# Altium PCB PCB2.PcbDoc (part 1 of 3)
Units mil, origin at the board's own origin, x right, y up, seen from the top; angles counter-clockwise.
Board outline 10275.59 x 4173.23 mil, 2 copper layers (Top Layer, Bottom Layer); 158 components, 159 nets, 776 pads, 338 vias.
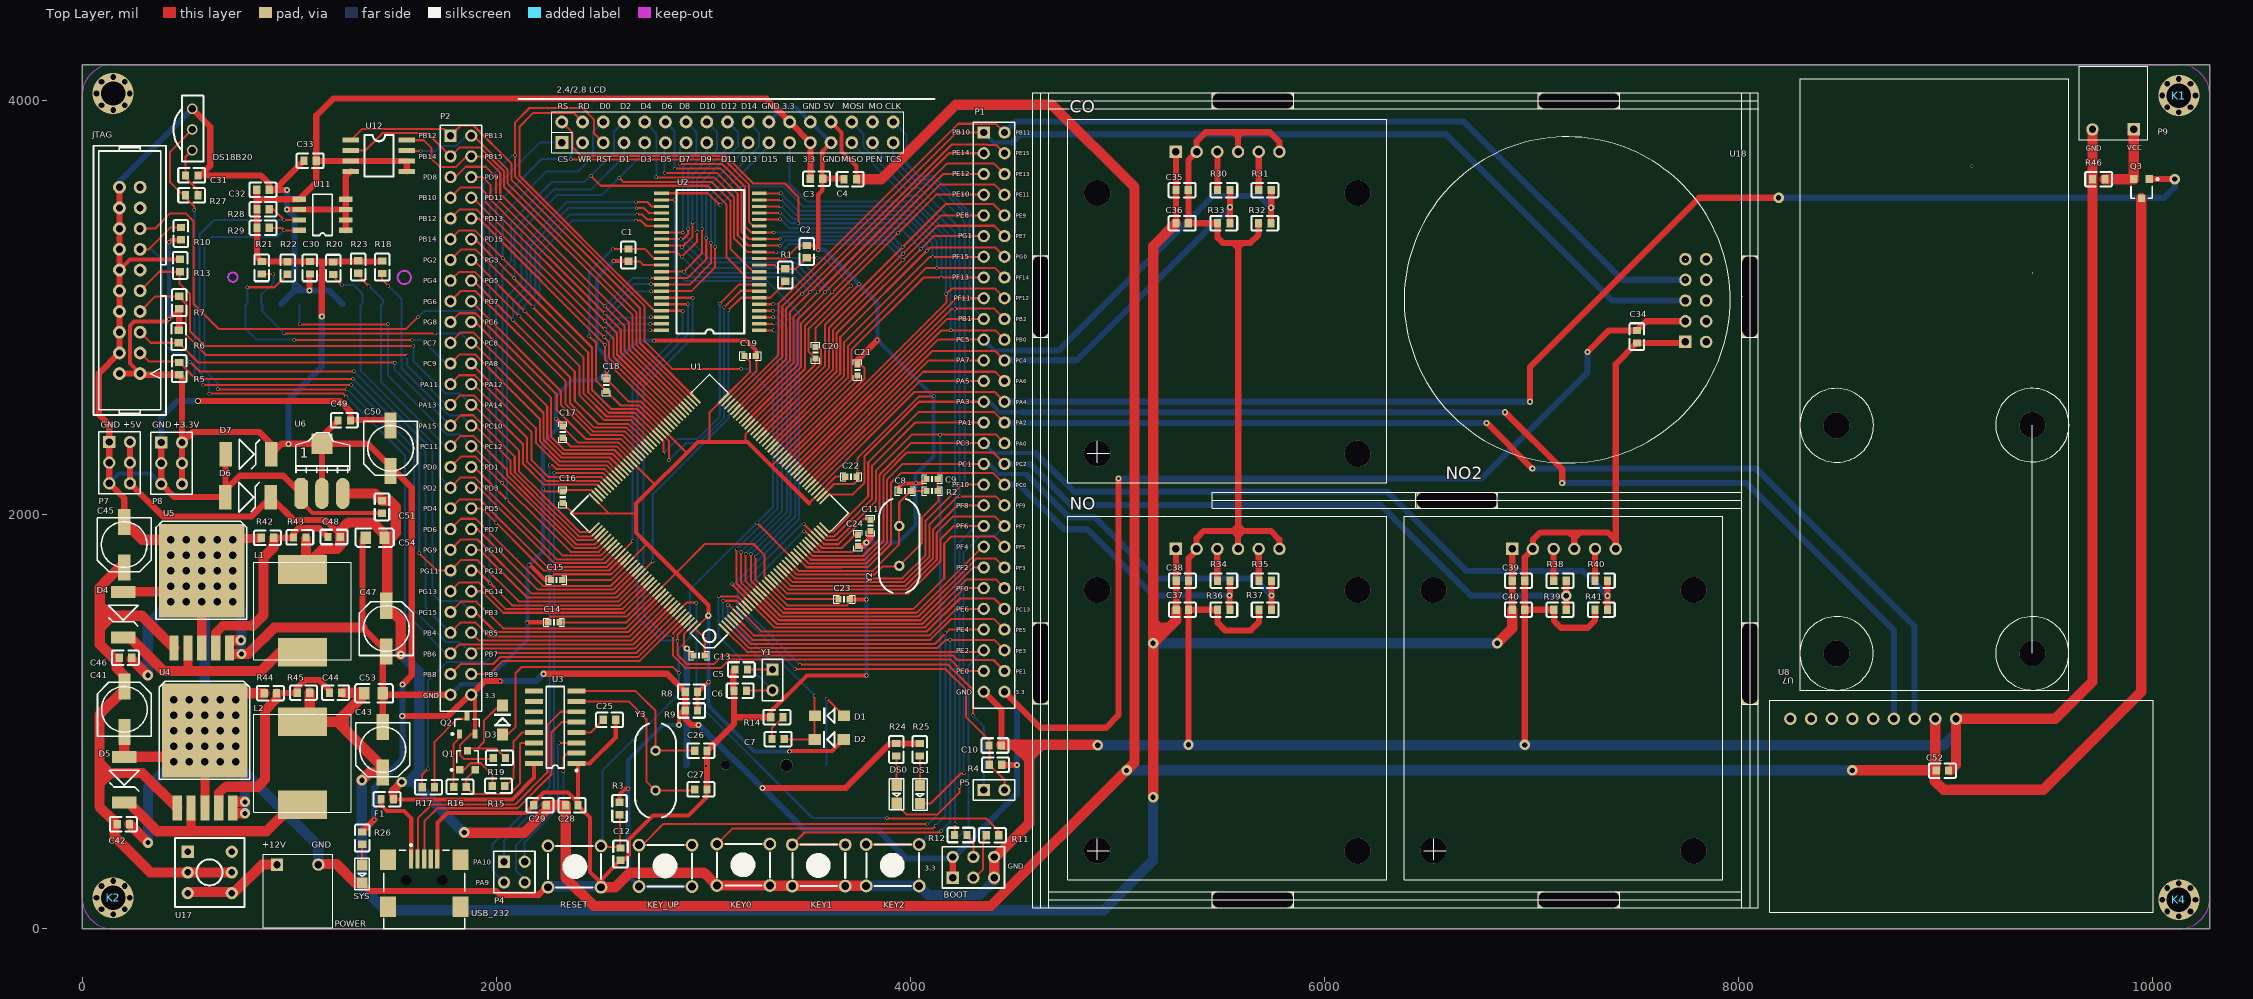
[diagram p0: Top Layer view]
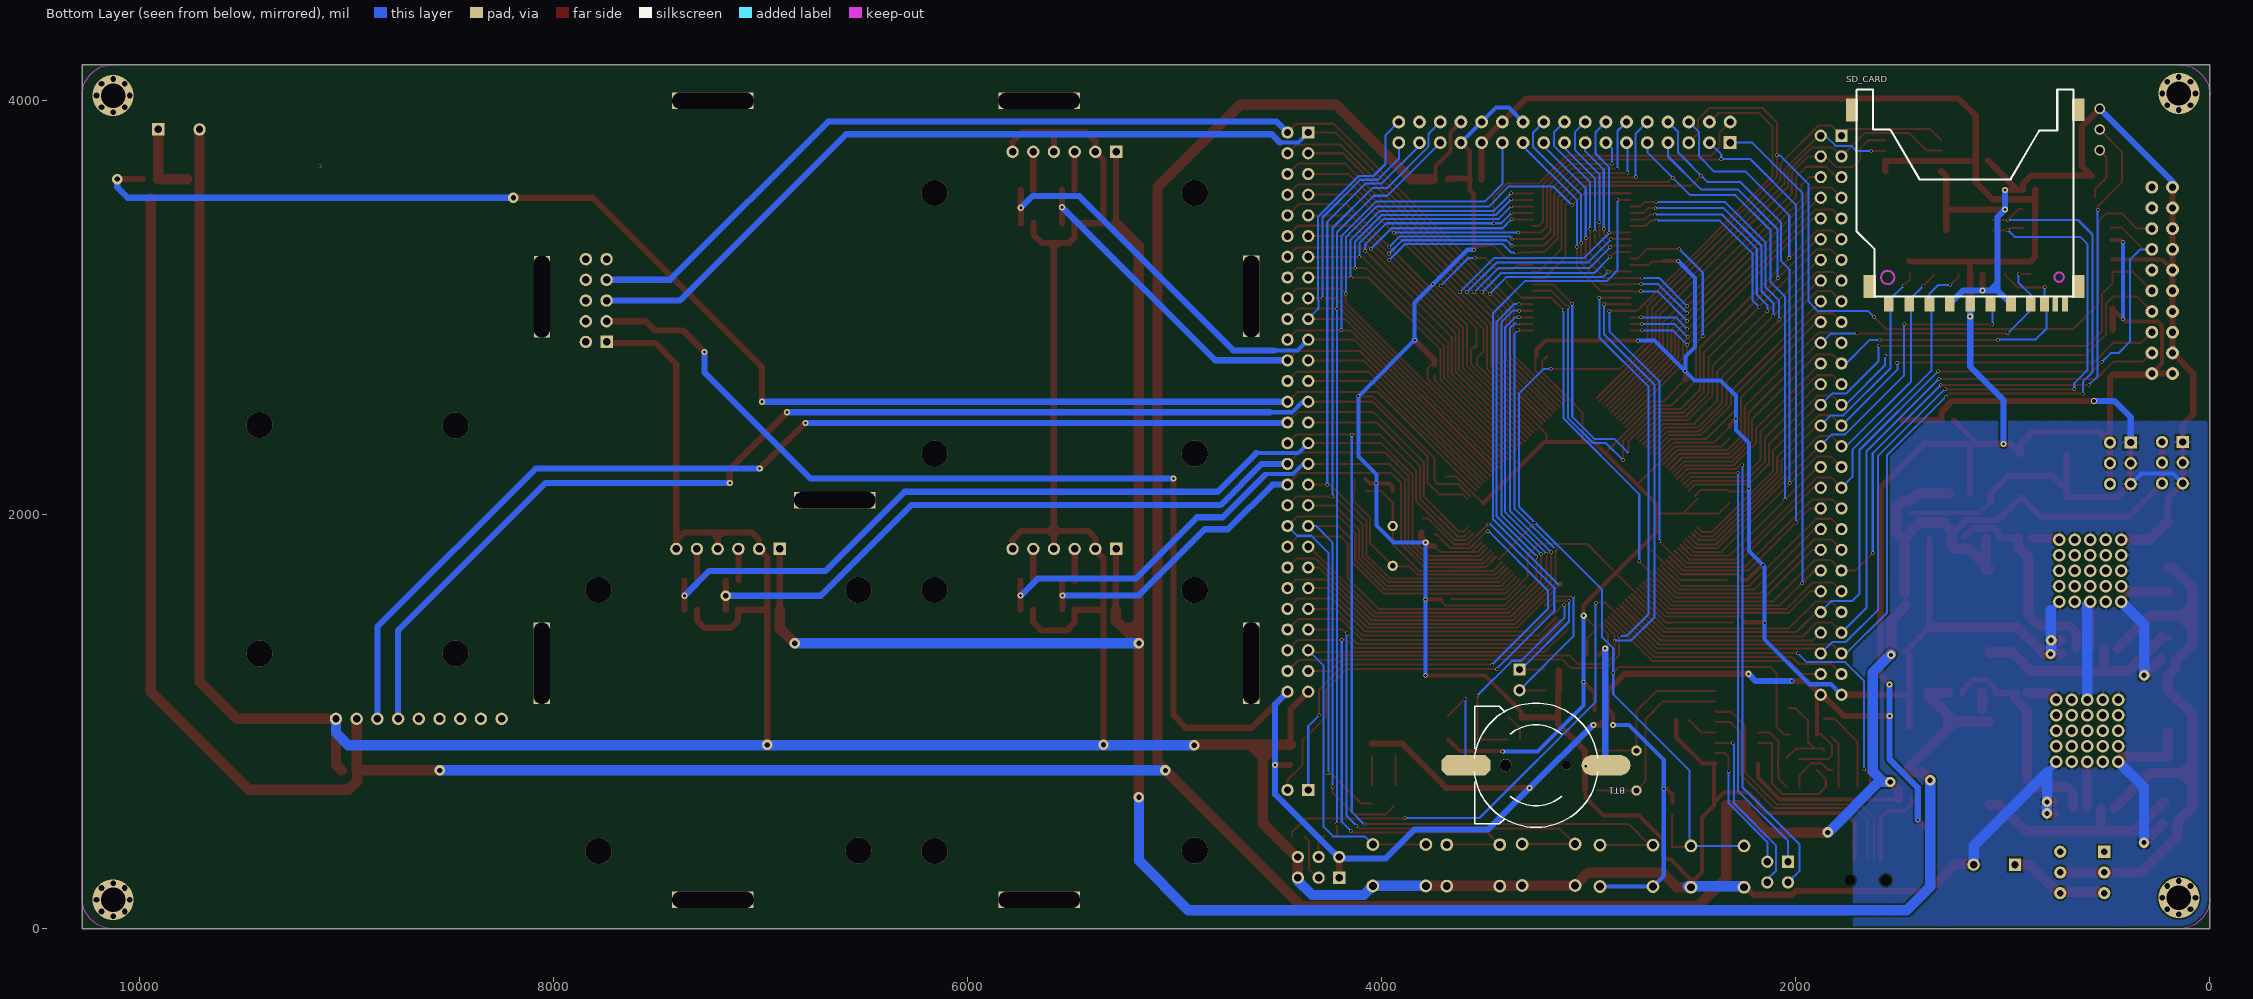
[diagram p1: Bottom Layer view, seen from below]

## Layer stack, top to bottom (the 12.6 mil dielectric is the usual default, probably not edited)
Top Layer: signal copper 1.4
Dielectric: dielectric 12.6, FR-4, Dk 4.8
Bottom Layer: signal copper 1.4

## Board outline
0,4173.23 10275.59,4173.23 10275.59,0 10217.37,0 0,0

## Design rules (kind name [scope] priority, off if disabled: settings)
Clearance [All] p1: gap=8
HoleSize [All] p1: absolutevalues=TRUE maxlimit=400 minlimit=1 maxpercent=80.000 minpercent=20.000
HoleToHoleClearance [All] p1: gap=5 allowstackedmicrovias=TRUE
PolygonConnect [All] p1: connectstyle=Relief reliefconductorwidth=10 reliefentries=4 polygonreliefangle="90 Angle" airgapwidth=10
RoutingVias [All] p1: holewidth=28 width=50 viastyle="Through Hole" minholewidth=28 minwidth=50 maxholewidth=28 maxwidth=50
SilkToSilkClearance [All] p1: silktosilkclearance=0
SilkToSolderMaskClearance [IsPad] p1: minsilkscreentomaskgap=0 clearancetoexposedcopper=TRUE
SolderMaskExpansion [All] p1: expansion=4
Width VCC3.3M [InNet('VCC3.3M')] p1: maxlimit=30 minlimit=10 preferedwidth=10
Width VCC3.3 [InNet('VCC3.3')] p2: maxlimit=30 minlimit=10 preferedwidth=10
Width VCC6 [InNet('VCC6')] p3: maxlimit=50 minlimit=10 preferedwidth=10
Width GND [InNet('GND')] p4: maxlimit=50 minlimit=10 preferedwidth=10
Width VCC5 [InNet('VCC5')] p5: maxlimit=50 minlimit=10 preferedwidth=10
Width [All] p6: maxlimit=50 minlimit=10 preferedwidth=10
24 further rules are at their usual default settings.

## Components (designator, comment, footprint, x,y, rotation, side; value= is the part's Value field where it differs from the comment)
"2.4/2.8 LCD" "TFT_LCD" LCD 3322,2791 r0 top
BOOT "Header 3X2" HDR2X3 4204.37,246.61 r0 top
BT1 "Battery" BATM 3254.37,789.61 r270 bottom
C1 "Cap" 0603A 2638.37,3282.61 r270 top
C2 "Cap" 0603A 3499.37,3239.61 r90 top
C3 "Cap" 0603A 3517,3622 r0 top
C4 "Cap" 0603A 3739.37,3619.61 r180 top
C5 "Cap" 0603A 3153.37,1251.61 r0 top
C6 "Cap" 0603A 3148.37,1149.61 r0 top
C7 "Cap" 0603A 3331.37,915.61 r0 top
C8 "Cap" 0603P 3974.37,2113.61 r0 top
C9 "Cap" 0603P 4104.37,2171.61 r0 top
C10 "Cap" 0603A 4439.37,884.61 r180 top
C11 "Cap" 0603P 3808,1947 r90 top
C12 "Cap" 0603A 2600,330 r90 top
C13 "Cap" 0603P 2979.37,1319.61 r0 top
C14 "Cap" 0603P 2278.37,1479.61 r0 top
C15 "Cap" 0603P 2291.37,1683.61 r0 top
C16 "Cap" 0603P 2321.37,2083.61 r270 top
C17 "Cap" 0603P 2321.37,2398.61 r270 top
C18 "Cap" 0603P 2531.37,2624.61 r270 top
C19 "Cap" 0603P 3226.37,2765.61 r180 top
C20 "Cap" 0603P 3541.37,2781.61 r270 top
C21 "Cap" 0603P 3744.37,2698.61 r270 top
C22 "Cap" 0603P 3713.37,2182.61 r180 top
C23 "Cap" 0603P 3680.37,1590.61 r180 top
C24 "Cap" 0603P 3746.37,1874.61 r90 top
C25 "Cap" 0603A 2517.37,1008.61 r0 top
C26 "Cap" 0603A 3018.37,859.61 r180 top
C27 "Cap" 0603A 3018.37,672.61 r180 top
C28 "Cap" 0603A 2395.37,595.61 r180 top
C29 "Cap" 0603A 2181.37,595.61 r0 top
C30 "Cap" 0603A 1100.37,3161.61 r90 top
C31 "Cap" 0603A 499.37,3637.61 r0 top
C32 "Cap" 0603A 843.37,3568.61 r0 top
C33 "Cap" 0603A 1131.37,3708.61 r180 top
C34 "Cap" 0603A 7508.37,2828.74 r90 top
C35 "Cap" 0603A 5282.37,3566.74 r0 top
C36 "Cap" 0603A 5282.37,3406.74 r0 top
C37 "Cap" 0603A 5283.37,1540.74 r0 top
C38 "Cap" 0603A 5283.37,1680.74 r0 top
C39 "Cap" 0603A 6906.37,1680.74 r0 top
C40 "Cap" 0603A 6906.37,1540.74 r0 top
C41 "Cap Pol2" CC6.56.5 204.37,1059.61 r270 top
C42 "Cap" 0603A 229.37,504.61 r180 top
C43 "Cap Pol1" CC6.56.5 1452.37,864.61 r90 top
C44 "Cap" 0603A 1254.37,1139.61 r180 top
C45 "Cap Pol2" CC6.56.5 203.37,1854.61 r90 top
C46 "Cap" 0603A 239.37,1308.61 r180 top
C47 "Cap Pol1" CC6.56.5 1469.37,1449.61 r270 top
C48 "Cap" 0603A 1247.37,1891.61 r180 top
C49 "Cap" 0603A 1236.37,2454.61 r0 top
C50 "Cap Pol1" CC6.56.5 1490,2320 r90 top
C51 "Cap" 0603A 1448.37,2066.61 r270 top
C52 "Cap" 0603A 8953.37,763.74 r0 top
C53 "Cap" 0805 1362.37,1136.61 r0 top
C54 "Cap" 0805 1460.24,1888.61 r180 top
CO "B4" chuanganqi 6299.91,2153.61 r90 top
D1 "1N4148" DIODE_SOP 3679.37,1027.61 r180 top
D2 "1N4148" DIODE_SOP 3678.37,913.61 r180 top
D3 "1N4148" DIODE_SOP 2030.37,937.61 r90 top
D4 "D1" SMBJ 199.37,1521.61 r270 top
D5 "D1" SMBJ 204.37,724.61 r270 top
D6 "SMBJ50.A" SMBJ 796.37,2084.61 r0 top
D7 "SMBJ3.3A" SMBJ 798.37,2291.61 r0 top
DS0 "LED0" SMDLED 3933.37,693.61 r270 top
DS1 "LED1" SMDLED 4046.37,691.61 r270 top
DS18B20 "Header 3" HS0038 532.37,3959.61 r270 top (schematic designator P6)
F1 "Res2" 0603A 1443.37,624.61 r0 top
JTAG "JTAG" JTAG_20 230.37,3130.61 r90 top
K1 "固定孔" 固定孔 10125.59,4023.23 r0 top
K2 "固定孔" 固定孔 150,150 r0 top
K3 "固定孔" 固定孔 150,4033.23 r0 top
K4 "固定孔" 固定孔 10125.59,140 r0 top
KEY0 "SW-PB" KEY_M 3321.37,208.61 r180 top
KEY1 "SW-PB" KEY_M 3685.37,205.61 r180 top
KEY2 "SW-PB" KEY_M 4042.37,206.61 r180 top
KEY_UP "SW-PB" KEY_M 2945.37,203.61 r180 top
L1 "Inductor" PCBComponent_1 1064.37,1534.61 r90 top
L2 "Inductor" PCBComponent_1 1064.37,799.61 r90 top
NO "B4" chuanganqi 6299.91,235.61 r90 top
NO2 "B4" chuanganqi 7923.88,235.61 r90 top
P1 "Header28X2" HEADER28X2 4354.37,3844.61 r270 top
P2 "Header28X2" HEADER28X2 1779.37,3829.61 r270 top
P4 "USART1" HDR2X2 2037.37,323.61 r270 top
P5 "Header 2" HDR1X2 4354.37,669.61 r0 top
P7 "Header 3X2" HDR2X3 131.37,2350.61 r270 top
P8 "Header 3X2" HDR2X3 382.37,2347.61 r270 top
P9 "Header 2" 接插件 9808.37,3809.74 r180 top
POWER "3-35V" 接插件 1041.37,359.74 r0 top (schematic designator IN)
Q1 "S8250" SOT-23R 1861.37,808.61 r0 top
Q2 "S8550" SOT-23B_N 1859.37,984.61 r90 top
Q3 "NPN" SOT-23R 9945.37,3578.61 r180 top
R1 "Res2" 0603A 3395.37,3126.61 r90 top
R2 "Res2" 0603P 4104.37,2113.61 r0 top
R3 "Res2" 0603A 2595.37,550.61 r90 top
R4 "10R" 0603A 4381.37,791.61 r0 top
R5 "Res2" 0603A 469.37,2674.61 r90 top
R6 "Res2" 0603A 466.37,2889.61 r270 top
R7 "Res2" 0603A 469.37,2993.61 r90 top
R8 "Res2" 0603A 2912.37,1144.61 r0 top
R9 "Res2" 0603A 2912.37,1053.61 r0 top
R10 "Res2" 0603A 477.37,3326.61 r90 top
R11 "Res2" 0603A 4366.37,451.61 r0 top
R12 "Res2" 0603A 4213.37,452.61 r0 top
R13 "Res2" 0603A 473.37,3172.61 r90 top
R14 "Res2" 0603A 3385.37,1021.61 r180 top
R15 "Res2" 0603A 1981.37,689.61 r0 top
R16 "Res2" 0603A 1795.37,684.61 r0 top
R17 "Res2" 0603A 1702.37,683.61 r180 top
R18 "Res2" 0603A 1449.37,3164.61 r90 top
R19 "Res2" 0603A 1985.37,824.61 r0 top
R20 "Res2" 0603A 1213.37,3219.61 r270 top
R21 "Res2" 0603A 867.37,3221.61 r270 top
R22 "Res2" 0603A 992.37,3220.61 r270 top
R23 "Res2" 0603A 1333.37,3225.61 r270 top
R24 "Res2" 0603A 3932.37,894.61 r270 top
R25 "Res2" 0603A 4045.37,894.61 r270 top
R26 "Res2" 0603A 1352.37,467.61 r270 top
R27 "Res2" 0603A 499.37,3541.61 r0 top
R28 "Res2" 0603A 844.37,3474.61 r0 top
R29 "Res2" 0603A 844.37,3384.61 r0 top
R30 "Res2" 0603A 5543.37,3566.74 r180 top
R31 "Res2" 0603A 5742.37,3566.74 r180 top
R32 "Res2" 0603A 5681.37,3406.74 r0 top
R33 "Res2" 0603A 5483.37,3406.74 r0 top
R34 "Res2" 0603A 5543.37,1680.74 r180 top
R35 "Res2" 0603A 5743.37,1680.74 r180 top
R36 "Res2" 0603A 5483.37,1540.74 r0 top
R37 "Res2" 0603A 5683.37,1540.74 r0 top
R38 "Res2" 0603A 7167.37,1680.74 r180 top
R39 "Res2" 0603A 7107.37,1540.74 r0 top
R40 "Res2" 0603A 7366.37,1680.74 r180 top
R41 "Res2" 0603A 7306.37,1540.74 r0 top
R42 "Res2" 0603A 925.37,1887.61 r180 top
R43 "Res2" 0603A 1021.37,1889.61 r0 top
R44 "Res2" 0603A 939.37,1137.61 r180 top
R45 "Res2" 0603A 1039.37,1139.61 r0 top
R46 "Res2" 0603A 9708.37,3619.61 r0 top
RESET "SW-PB" KEY_M 2250,400 r0 top
SD_CARD "SD_CARD" SDCARD_L 1452.37,3016.61 r0 bottom
SYS "PWR" SMDLED 1352.37,307.61 r270 top
U1 "stm32f103zet6" LQFP144 3099.6,1449.34 r135 top
U2 "IS62WV51216" TSOP44 3270.37,2889.61 r180 top
U3 "CH340G" SOP16M 2285.37,972.61 r90 top
U4 "LM2596ADJ" lm2596 592.37,956.61 r0 top
U5 "LM2596ADJ" lm2596 577.37,1728.61 r0 top
U6 "AMS1117-3.3" AMS1117 1058.37,2101.61 r0 top
U7 "qibeng" qibeng 9594.91,1152.61 r90 top
U8 "wuxian" wuxain 9049.37,1013.74 r270 top
U11 "24C02" SOP-8 1273.37,3372.61 r180 top
U12 "W25Q25" SOIC-8 1298.37,3807.61 r0 top
U17 "BUTTON" BTN8.5*8.5 510.37,371.74 r0 top
U18 "CO2" CO2 7171.91,3036.61 r0 top
USB_232 "USB" USB/SM0.8-6H5 1652.37,27.74 r270 top
Y1 "32.768K" HDR1X2 3334.37,1251.61 r270 top
Y2 "8M" XTAL_US 3946.37,1944.61 r270 top
Y3 "12MHZ" XTAL_US 2769.37,859.61 r270 top

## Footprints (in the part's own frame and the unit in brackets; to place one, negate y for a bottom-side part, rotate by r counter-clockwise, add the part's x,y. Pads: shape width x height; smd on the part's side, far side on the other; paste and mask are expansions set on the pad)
0603A [mil]
  rect 35x40 smd: 1(0,0) 2(60,0)
  silkscreen extent -35,-35 95,35
0603P [mil]
  rect 30x30 smd: 1(-27,0) 2(27.5,-0.06)
  silkscreen extent -50,-20 50,20
0805 [mil]
  rect 50x60 smd: 1(90,0) 2(0,0)
  silkscreen extent -45,-45 140,45
AMS1117 [mil]
  oct 65x150 smd: 1(0.03,-0.06)
  oval 65x150 smd: 2(100.03,-0.06) 3(200.03,-0.06)
  rect 100x100 smd: 4(100.03,239.94)
  silkscreen extent -26,100 234,293
BATM [mm]
  round 1.1 hole 1.1 unplated: 0(0,3.748)
  round 1.5 hole 1.5 unplated: 0(0.025,-3.752)
  oct 2.5x6 smd mask+0.102: 1(0,-8.602)
  oval 2.5x6 smd: 2(0,8.598)
  silkscreen extent -7.62,-7.58 7.62,7.57
BTN8.5*8.5 [mm]
  rect 1.5x1.5 hole 0.8: 1(0,0)
  round 1.5 hole 0.8: 2(0,-2.54) 3(0,-5.08) 4(5.4,-5.08) 5(5.4,-2.54) 6(5.4,0)
  silkscreen extent -1.55,-6.79 6.95,1.71
CC6.56.5 [mm]
  rect 3.2x1.5 smd: 1(-2.794,0) 2(2.8,0)
  silkscreen extent -3.3,-3.3 3.3,3.3
chuanganqi [mil]
  rect 60x60 hole 36: 1(1598.24,1017.72)
  round 60 hole 36: 2(1598.24,917.72) 3(1598.24,817.72) 4(1598.24,717.72) 5(1598.24,617.72) 6(1598.24,517.72)
  silkscreen extent 0,0 1756,1539
CO2 [mil]
  rect 60x60 hole 36: 1(570.87,-203.15)
  round 60 hole 36: 2(670.87,-203.15) 3(570.87,-103.15) 4(670.87,-103.15) 5(570.87,-3.15) 6(670.87,-3.15) 7(570.87,96.85) 8(670.87,96.85) 9(570.87,196.85) 10(670.87,196.85)
  silkscreen extent -787,-787 787,787
DIODE_SOP [mm]
  rect 1.5x1.3 smd: 1(0,0) 2(3.556,0)
  silkscreen extent 1.14,-1.02 2.56,1.02
HDR1X2 [mm] "Connector; Header; 2 Position"
  rect 1.5x1.5 hole 0.9: 1(0,0)
  round 1.5 hole 0.9: 2(2.54,0)
  silkscreen extent -1.27,-1.27 3.81,1.27
HDR2X2 [mm] "Connector; Header; 2x2 Position"
  rect 1.5x1.5 hole 0.9: 1(0,0)
  round 1.5 hole 0.9: 2(0,2.54) 3(2.54,0) 4(2.54,2.54)
  silkscreen extent -1.27,-1.27 3.81,3.81
HDR2X3 [mm] "Connector; Header; 3x2 Position"
  rect 1.5x1.5 hole 0.9: 1(0,0)
  round 1.5 hole 0.9: 2(0,2.54) 3(2.54,0) 4(2.54,2.54) 5(5.08,0) 6(5.08,2.54)
  silkscreen extent -1.27,-1.27 6.35,3.81
HEADER28X2 [mm]
  rect 1.5x1.5 hole 0.9: 1(0,0)
  round 1.5 hole 0.9: 2(0,2.54) 3(2.54,0) 4(2.54,2.54) 5(5.08,0) 6(5.08,2.54) 7(7.62,0) 8(7.62,2.54) 9(10.16,0) 10(10.16,2.54) 11(12.7,0) 12(12.7,2.54) 13(15.24,0) 14(15.24,2.54) 15(17.78,0) 16(17.78,2.54) 17(20.32,0) 18(20.32,2.54) 19(22.86,0) 20(22.86,2.54) 21(25.4,0) 22(25.4,2.54) 23(27.94,0) 24(27.94,2.54) 25(30.48,0) 26(30.48,2.54) 27(33.02,0) 28(33.02,2.54) 29(35.56,0) 30(35.56,2.54) 31(38.1,0) 32(38.1,2.54) 33(40.64,0) 34(40.64,2.54) 35(43.18,0) 36(43.18,2.54) 37(45.72,0) 38(45.72,2.54) 39(48.26,0) 40(48.26,2.54) 41(50.8,0) 42(50.8,2.54) 43(53.34,0) 44(53.34,2.54) 45(55.88,0) 46(55.88,2.54) 47(58.42,0) 48(58.42,2.54) 49(60.96,0) 50(60.96,2.54) 51(63.5,0) 52(63.5,2.54) 53(66.04,0) 54(66.04,2.54) 55(68.58,0) 56(68.58,2.54)
  silkscreen extent -1.27,-1.27 70.61,3.81
HS0038 [mm]
  round 1.3 hole 0.889: 1(0,0) 2(2.54,0) 3(5.08,0)
  silkscreen extent -1.65,-2.32 6.48,1.4
JTAG_20 [mil]
  round 62 hole 35: 1(-450,-50) 2(-450,50) 3(-350,-50) 4(-350,50) 5(-250,-50) 6(-250,50) 7(-150,-50) 8(-150,50) 9(-50,-50) 10(-50,50) 11(50,-50) 12(50,50) 13(150,-50) 14(150,50) 15(250,-50) 16(250,50) 17(350,-50) 18(350,50) 19(450,-50) 20(450,50)
  silkscreen extent -650,-175 650,175
KEY_M [mil]
  round 62 hole 38: 1(0,0) 1(255.91,0) 2(0,-200) 2(255.91,-200)
  silkscreen extent 0,-200 255,0
LCD [mil]
  rect 62x62 hole 35: 1(-1005,1005)
  round 62 hole 35: 2(-1005,1105) 3(-905,1005) 4(-905,1105) 5(-805,1005) 6(-805,1105) 7(-705,1005) 8(-705,1105) 9(-605,1005) 10(-605,1105) 11(-505,1005) 12(-505,1105) 13(-405,1005) 14(-405,1105) 15(-305,1005) 16(-305,1105) 17(-205,1005) 18(-205,1105) 19(-105,1005) 20(-105,1105) 21(-5,1005) 22(-5,1105) 23(95,1005) 24(95,1105) 25(195,1005) 26(195,1105) 27(295,1005) 28(295,1105) 29(395,1005) 30(395,1105) 31(495,1005) 32(495,1105) 33(595,1005) 34(595,1105)
  silkscreen extent -1215,955 795,1215
lm2596 [mil]
  rect 45x120 smd: 1(-133,-373.35) 2(-66,-373.35) 3(1,-373.35) 4(68,-373.35) 5(135,-373.35)
  rect 413.39x452.76 smd: 3(0,0)
  silkscreen extent -220,-235 217,239
LQFP144 [mil]
  rect 70.87x10 smd: 1(-0.35,0.02) 2(-0.35,-19.66) 3(-0.35,-39.35) 4(-0.35,-59.03) 5(-0.35,-78.72) 6(-0.35,-98.4) 7(-0.35,-118.09) 8(-0.35,-137.77) 9(-0.35,-157.46) 10(-0.35,-177.14) 11(-0.35,-196.83) 12(-0.35,-216.51) 13(-0.35,-236.2) 14(-0.35,-255.88) 15(-0.35,-275.57) 16(-0.35,-295.25) 17(-0.35,-314.94) 18(-0.35,-334.62) 19(-0.35,-354.31) 20(-0.35,-373.99) 21(-0.35,-393.68) 22(-0.35,-413.36) 23(-0.35,-433.05) 24(-0.35,-452.73) 25(-0.35,-472.42) 26(-0.35,-492.1) 27(-0.35,-511.79) 28(-0.35,-531.47) 29(-0.35,-551.16) 30(-0.35,-570.84) 31(-0.35,-590.53) 32(-0.35,-610.21) 33(-0.35,-629.9) 34(-0.35,-649.58) 35(-0.35,-669.27) 36(-0.35,-688.95) 73(885.47,-688.95) 74(885.47,-669.27) 75(885.47,-649.58) 76(885.47,-629.9) 77(885.47,-610.21) 78(885.47,-590.53) 79(885.47,-570.84) 80(885.47,-551.16) 81(885.47,-531.47) 82(885.47,-511.79) 83(885.47,-492.1) 84(885.47,-472.42) 85(885.47,-452.73) 86(885.47,-433.05) 87(885.47,-413.36) 88(885.47,-393.68) 89(885.47,-373.99) 90(885.47,-354.31) 91(885.47,-334.62) 92(885.47,-314.94) 93(885.47,-295.25) 94(885.47,-275.57) 95(885.47,-255.88) 96(885.47,-236.2) 97(885.47,-216.51) 98(885.47,-196.83) 99(885.47,-177.14) 100(885.47,-157.46) 101(885.47,-137.77) 102(885.47,-118.09) 103(885.47,-98.4) 104(885.47,-78.72) 105(885.47,-59.03) 106(885.47,-39.35) 107(885.47,-19.66) 108(885.47,0.02)
  rect 10x70.87 smd: 37(98.07,-787.38) 38(117.76,-787.38) 39(137.44,-787.38) 40(157.13,-787.38) 41(176.81,-787.38) 42(196.5,-787.38) 43(216.18,-787.38) 44(235.87,-787.38) 45(255.55,-787.38) 46(275.24,-787.38) 47(294.92,-787.38) 48(314.61,-787.38) 49(334.29,-787.38) 50(353.98,-787.38) 51(373.66,-787.38) 52(393.35,-787.38) 53(413.03,-787.38) 54(432.72,-787.38) 55(452.4,-787.38) 56(472.09,-787.38) 57(491.77,-787.38) 58(511.46,-787.38) 59(531.14,-787.38) 60(550.83,-787.38) 61(570.51,-787.38) 62(590.2,-787.38) 63(609.88,-787.38) 64(629.57,-787.38) 65(649.25,-787.38) 66(668.94,-787.38) 67(688.62,-787.38) 68(708.31,-787.38) 69(727.99,-787.38) 70(747.68,-787.38) 71(767.36,-787.38) 72(787.05,-787.38) 109(787.05,98.45) 110(767.36,98.45) 111(747.68,98.45) 112(727.99,98.45) 113(708.31,98.45) 114(688.62,98.45) 115(668.94,98.45) 116(649.25,98.45) 117(629.57,98.45) 118(609.88,98.45) 119(590.2,98.45) 120(570.51,98.45) 121(550.83,98.45) 122(531.14,98.45) 123(511.46,98.45) 124(491.77,98.45) 125(472.09,98.45) 126(452.4,98.45) 127(432.72,98.45) 128(413.03,98.45) 129(393.35,98.45) 130(373.66,98.45) 131(353.98,98.45) 132(334.29,98.45) 133(314.61,98.45) 134(294.92,98.45) 135(275.24,98.45) 136(255.55,98.45) 137(235.87,98.45) 138(216.18,98.45) 139(196.5,98.45) 140(176.81,98.45) 141(157.13,98.45) 142(137.44,98.45) 143(117.76,98.45) 144(98.07,98.45)
  silkscreen extent -32,-819 917,130
PCBComponent_1 [mm]
  rect 3.5x6 smd: 1(-5.08,0) 2(5.08,0)
  silkscreen extent -6,-5.99 6,6.01
qibeng [mil]
  silkscreen extent 0,0 2953,1300
SDCARD_L [mm]
  rect 1.2x1.8 smd: 1(0,0) 2(-2.489,0) 3(-4.983,-0.009) 4(-7.483,-0.009) 5(-9.983,-0.009) 6(-12.483,-0.009) 7(-14.908,-0.009) 9(2.517,-0.009)
  rect 1.1x1.8 smd: 8(-16.612,0)
  rect 0.7x1.8 smd: 10(-17.908,-0.009) 12(-19.101,0)
  rect 1.5x2.8 smd: 11(-20.726,-23.834) 11(-20.726,-2.143) 11(4.826,-2.143) 11(7.01,-23.784)
  Keep-Out Layer circle w0.254: c2.642,-3.26 r0.82
  Keep-Out Layer circle w0.254: c-18.39,-3.3 r0.58
  silkscreen extent -20.13,-26.3 6.44,-0.9
SMBJ [mm]
  rect 1.5x3 smd: 1(-2.667,0) 2(2.921,0)
  silkscreen extent -1.02,-1.85 1.52,1.83
SMDLED [mm]
  rect 1.4x1.27 smd: 1(0.001,-0.002) 2(2.211,-0.002)
  silkscreen extent -0.8,-0.89 3.01,0.89
SOIC-8 [mil]
  rect 80x24 smd: 1(0,0) 2(0,-50.06) 3(0,-100.06) 4(0,-150.06) 5(270,-150) 6(270,-100) 7(270,-50) 8(270,0)
  silkscreen extent 65,-175 205,25
SOP16M [mm]
  rect 0.6x2.2 smd: 1(-4.445,-2.6) 2(-3.175,-2.6) 3(-1.905,-2.6) 4(-0.635,-2.6) 5(0.635,-2.6) 6(1.905,-2.6) 7(3.175,-2.6) 8(4.445,-2.6) 9(4.445,2.6) 10(3.175,2.6) 11(1.905,2.6) 12(0.635,2.6) 13(-0.635,2.6) 14(-1.905,2.6) 15(-3.175,2.6) 16(-4.445,2.6)
  silkscreen extent -5.42,-2.72 5,1.1
SOP-8 [mil]
  rect 65x25 smd: 1(0,0) 2(0,-50) 3(0,-100) 4(0,-150) 5(224.41,-150) 6(224.41,-100) 7(224.41,-50) 8(224.41,0)
  silkscreen extent 65,-175 159,25
SOT-23B_N [mm] "SOT23, 3-Leads, Body 2.9x1.3mm, Pitch 0.95mm, Lead Span 2.4mm, IPC Medium Density"
  rect 1.15x0.6 smd: 1(-1.125,0.95) 2(-1.125,-0.95) 3(1.125,0)
  silkscreen extent -1.25,-1.5 0.7,1.92, body extent -0.7,-1.5 0.7,1.5, height 1.14
SOT-23R [mm]
  rect 0.9x0.95 smd: 1(-0.95,-1.048) 2(0.95,-1.048) 3(0,1.302)
  silkscreen extent -2.07,-1.17 1.3,1.3
TSOP44 [mm]
  rect 1.8x0.4 smd: 1(-0.009,0.001) 2(-0.009,-0.799) 3(-0.009,-1.599) 4(-0.009,-2.399) 5(-0.009,-3.199) 6(-0.009,-3.999) 7(-0.009,-4.799) 8(-0.009,-5.599) 9(-0.009,-6.399) 10(-0.009,-7.199) 11(-0.009,-7.999) 12(-0.009,-8.799) 13(-0.009,-9.599) 14(-0.009,-10.399) 15(-0.009,-11.199) 16(-0.009,-11.999) 17(-0.009,-12.799) 18(-0.009,-13.599) 19(-0.009,-14.399) 20(-0.009,-15.199) 21(-0.009,-15.999) 22(-0.009,-16.799) 23(11.991,-16.799) 24(11.991,-15.999) 25(11.991,-15.199) 26(11.991,-14.399) 27(11.991,-13.599) 28(11.991,-12.799) 29(11.991,-11.999) 30(11.991,-11.199) 31(11.991,-10.399) 32(11.991,-9.599) 33(11.991,-8.799) 34(11.991,-7.999) 35(11.991,-7.199) 36(11.991,-6.399) 37(11.991,-5.599) 38(11.991,-4.799) 39(11.991,-3.999) 40(11.991,-3.199) 41(11.991,-2.399) 42(11.991,-1.599) 43(11.991,-0.799) 44(11.991,0.001)
  silkscreen extent 1.83,-17.2 10.16,0.4
USB/SM0.8-6H5 [mm]
  rect 2.3x0.5 smd: 1(-7.85,-1.6) 2(-7.85,-0.8) 3(-7.85,0) 4(-7.85,0.8) 5(-7.85,1.6)
  rect 2.5x2 smd: 6(-7.75,4.45) 7(-1.996,4.45) 8(-7.75,-4.45) 9(-1.996,-4.45)
  round 0.6 hole 1.27 unplated: MH1(-5.25,2.2) MH2(-5.25,-2.2)
  silkscreen extent -9.67,-4.95 0.7,4.95
wuxain [mil]
  round 60 hole 36: 1(0,0) 2(0,-100) 3(0,-200) 4(0,-300) 5(0,-400) 6(0,-500) 7(0,-600) 8(0,-700) 9(0,-800)
  silkscreen extent -91,-900 933,953
XTAL_US [mil]
  round 50 hole 28: 1(0,0) 2(192.13,0)
  silkscreen extent -131,-98 323,98
固定孔 [mil]
接插件 [mil]
  rect 60x60 hole 36: 1(-100,-50)
  round 60 hole 36: 2(100,-50)
  silkscreen extent -167,-354 167,0

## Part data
BOOT P7 P8: "Header, 3-Pin, Dual row"
BT1: "Multicell Battery"
C1 C2 C3 C4 C5 C6 C7 C8 C9 C10 C11 C12 C13 C14 C15 C16 C17 C18 C19 C20 C21 C22 C23 C24 C25 C26 C27 C28 C29 C30 C31 C32 C33 C34 C35 C36 C37 C38 C39 C40 C42 C44 C46 C48 C49 C51 C52 C53 C54: "Capacitor"
C41 C45: "Polarized Capacitor (Axial)"
C43 C47 C50: "Polarized Capacitor (Radial)"
D1 D2: library part "Diode 1N4148", "High Conductance Fast Diode"
D3: library part "Diode BAS116", "Silicon Low Leakage Diode"
D6 D7: library part D1
DS0: "Typical INFRARED GaAs LED"
DS1 SYS: library part LED0, "Typical INFRARED GaAs LED"
DS18B20: "Header, 3-Pin"
F1 R1 R2 R3 R5 R6 R7 R8 R9 R10 R11 R12 R13 R14 R15 R16 R17 R18 R19 R20 R21 R22 R23 R24 R25 R26 R27 R28 R29 R30 R31 R32 R33 R34 R35 R36 R37 R38 R39 R40 R41 R42 R43 R44 R45 R46: "Resistor"
KEY0 KEY1 KEY2 KEY_UP RESET: "Switch"
P4: library part "Header 2X2", "Header, 2-Pin, Dual row"
P5 P9: "Header, 2-Pin"
POWER: library part "Header 2", "Header, 2-Pin"
Q1: library part NPN, "NPN Bipolar Transistor"
Q2: library part PNP, "PNP Bipolar Transistor"
Q3: "NPN Bipolar Transistor"
R4: library part Res2, "Resistor"
Y1 Y2 Y3: library part XTAL, "Crystal Oscillator"

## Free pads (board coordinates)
  rect 393.7x78.74 hole 78.74 slot 393.7 at 0 deg: 1(5652.91,139.98) 2(7228.91,139.98) 7(5653.91,3997.61) 8(7228.91,3997.87) 9(6640.69,2069.74)
  rect 78.74x393.7 hole 78.74 slot 393.7 at 90 deg: 3(4629.91,1282.61) 4(4629.91,3053.61) 5(8055.72,1281.61) 6(8054.91,3052.61)

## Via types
v1: diameter 16, hole 12, Top Layer to Bottom Layer, 183 vias
v2: diameter 60, hole 36, Top Layer to Bottom Layer, 50 vias
v3: diameter 27.56, hole 27.56, Top Layer to Bottom Layer, 32 vias
v4: diameter 30, hole 15, Top Layer to Bottom Layer, 27 vias
v5: diameter 50, hole 25, Top Layer to Bottom Layer, 19 vias
v6: diameter 125.98, hole 125.98, Top Layer to Bottom Layer, 16 vias
v7: diameter 20, hole 15, Top Layer to Bottom Layer, 4 vias
v8: diameter 196.85, hole 118.11, Top Layer to Bottom Layer, 4 vias
v9: diameter 30, hole 20, Top Layer to Bottom Layer, 1 vias
v10: diameter 40, hole 20, Top Layer to Bottom Layer, 1 vias
v11: diameter 50, hole 28, Top Layer to Bottom Layer, 1 vias

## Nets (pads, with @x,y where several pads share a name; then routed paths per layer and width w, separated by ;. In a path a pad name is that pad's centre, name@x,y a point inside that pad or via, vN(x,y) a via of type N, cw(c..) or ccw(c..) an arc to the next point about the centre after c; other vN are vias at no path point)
BOOT0: R11.2 R17.2 U1.138 | length 4204.2
  Top Layer w10: R17.2@1642.37,683.61 1642.37,744.61 v1(1669.37,771.61) ; v1(1991.37,1330.61) 2675.15,1330.61 U1.138@2877.13,1532.59 ; U1.138@2876.89,1532.86 2918.64,1574.61 v1(2966.37,1574.61) ; v1(3885.37,534.61) 3887.37,532.61 4365.37,532.61 4433.37,464.61 R11.2@4433.37,445.61
  Bottom Layer w10: v1(1669.37,771.61) 1670.37,772.61 1670.37,1196.75 1761.23,1287.61 1761.75,1287.08 1947.84,1287.08 v1(1991.37,1330.61) ; v1(2966.37,1574.61) 2966.37,1095.61 3527.37,534.61 v1(3885.37,534.61)
BOOT1: "2.4/2.8 LCD.29" P1.20 R12.1 U1.48 | length 4951
  Top Layer w10: U1.48@3433.9,2228.56 4198.95,2993.61 v1(4215.37,2993.61) ; R12.1@4215.37,447.61 v1(4215.37,507.61) ; v1@4215.37,2994.61 4404.37,2994.61 P1.20@4454.37,2944.61
  Bottom Layer w10: 3717,3796 3973.39,3539.61 4038.37,3539.61 4215.37,3362.61 v1(4215.37,2993.61) v1(4215.37,507.61)
CH340_D+: U3.5 USB_232.3 | length 1243.6
  Top Layer w10: USB_232.3@1653.37,326.74 1653.37,518.61 1716.37,581.61 2103.37,581.61 2266.37,744.61 2266.37,947.61 2316.37,997.61 U3.5@2387.73,997.61
CH340_D-: U3.6 USB_232.2 | length 1313.1
  Top Layer w10: USB_232.2@1621.37,332.74 1621.37,532.61 1688.37,599.61 2091.37,599.61 2246.37,754.61 2246.37,982.61 2311.37,1047.61 U3.6@2387.73,1047.61
CO_1: P1.24 R30.1 R33.2 U1.44 | length 2794.2
  Top Layer w10: U1.44@3489.35,2173.15 4105.81,2789.61 4409.37,2789.61 P1.24@4454.37,2744.61
  Top Layer w30: R33.2@5543.37,3406.74 v4(5543.37,3483.74) R30.1@5543.37,3566.74
  Bottom Layer w30: P1.24@4454.37,2744.61 4804.24,2744.61 v4(5543.37,3483.74)
CO_2: P1.21 R31.1 R32.2 U1.45 | length 3052.4
  Top Layer w10: U1.45@3475.43,2187.07 4132.97,2844.61 P1.21@4354.37,2844.61
  Top Layer w30: R32.2@5741.37,3406.74 v4@5741.37,3480.74 ; v4(5742.37,3481.74) R31.1@5742.37,3566.74
  Bottom Layer w20: P1.21@4354.37,2844.61 4406.37,2792.61 4518.91,2792.61
  Bottom Layer w30: 4518.91,2792.61 4716.91,2792.61 5462.91,3538.61 5685.5,3538.61 v4(5742.37,3481.74)
DS18B20: DS18B20.2 P2.43 R27.1 U1.126 | length 4278.1
  Top Layer w10: DS18B20.2@532.37,3859.61 425.37,3752.61 425.37,3604.61 542.37,3487.61 v1(542.37,3472.61) ; v1(584.37,2625.61) v1(1299.37,2625.61) ; v1(1628.37,1813.61) 1712.37,1729.61 P2.43@1779.37,1729.61 1829.37,1779.61 1909.37,1779.61 2108.37,1580.61 2591.08,1580.61 U1.126@2710.09,1699.62
  Bottom Layer w10: v1@539.37,3473.61 v1@541.37,3473.61 ; v1(542.37,3472.61) 542.37,2668.61 v1@584.87,2626.11 ; v1(1299.37,2625.61) 1628.37,2296.61 v1(1628.37,1813.61)
F_CS: P2.1 U1.73 U12.1 | length 2408.6
  Top Layer w10: U12.1@1298.37,3807.61 1353.37,3862.61 1746.37,3862.61 P2.1@1779.37,3829.61 1828.37,3878.61 1890.51,3878.61 2073.37,3695.75 2073.37,3617.61 2694.37,2996.61 2694.37,2828.15 2959.9,2562.62 U1.73@2960.64,2562.62
FSMC_A0: P1.45 U1.10 U2.24 | length 3925
  Top Layer w10: U2.24@2798.28,3519.5 v1(2861.27,3519.5) ; v1(3137.37,1664.61) U1.10@3225.11,1574.35 ; U1.10@3224.88,1574.61 3345.89,1453.61 4068.37,1453.61 4259.37,1644.61 P1.45@4354.37,1644.61
  Bottom Layer w10: v1(2861.27,3519.5) 2861.27,3178.61 2911.27,3128.61 3306.37,3128.61 3462.37,2972.61 3462.37,1976.91 3150.07,1664.61 v1(3137.37,1664.61)
FSMC_A1: P1.46 U1.11 U2.1 | length 2862.1
  Top Layer w10: v1(3160.37,1831.61) 3160.37,1666.96 3355.72,1471.61 4056.37,1471.61 4271.9,1687.13 4411.84,1687.13 P1.46@4454.37,1644.61 ; U2.1@3270.72,2889.58 v1(3339.37,2889.61)
  Bottom Layer w10: v1(3160.37,1831.61) 3267.37,1938.61 3268.07,1938.61 3357.37,2027.91 3357.37,2872.61 v1@3340.37,2889.61
FSMC_A2: P1.43 U1.12 U2.2 | length 2780.8
  Top Layer w10: v1(3181.37,1818.61) 3181.37,1673.8 3365.56,1489.61 4048.91,1489.61 4303.91,1744.61 P1.43@4354.37,1744.61 ; U2.2@3270.72,2921.08 v1@3337.84,2921.08
  Bottom Layer w10: v1(3181.37,1818.61) 3380.37,2017.61 3380.37,2899.61 3357.37,2922.61 v1(3339.37,2922.61)
FSMC_A3: P1.44 U1.13 U2.3 | length 2917
  Top Layer w10: v1(3205.37,1811.61) 3203.37,1809.61 3203.37,1679.64 3375.4,1507.61 4037.83,1507.61 4317.35,1787.13 4411.84,1787.13 P1.44@4454.37,1744.61 ; U2.3@3270.72,2952.57 v1(3337.34,2952.57)
  Bottom Layer w10: v1@3203.37,1811.61 3403.64,2011.88 3403.64,2904.33 3355.4,2952.57 v1(3337.34,2952.57)
FSMC_A4: P1.41 U1.14 U2.4 | length 2820.7
  Top Layer w10: v1(3229.37,1807.61) 3229.37,1681.48 3385.24,1525.61 4030.37,1525.61 4349.37,1844.61 P1.41@4354.37,1844.61 ; U2.4@3270.72,2984.07 v1@3335.37,2984.07
  Bottom Layer w10: v1(3229.37,1807.61) 3421.64,1999.88 3421.64,2928.88 3365.91,2984.61 v1@3337.37,2984.61
  other v1: 3335.37,2984.61
FSMC_A5: P1.42 U1.15 U2.5 | length 3060.1
  Top Layer w10: v1(3252.37,1796.61) 3251.37,1795.61 3251.37,1687.32 3395.08,1543.61 4014.61,1543.61 4163.37,1692.37 4163.37,1859.61 4198.37,1894.61 4404.37,1894.61 P1.42@4454.37,1844.61 ; U2.5@3270.72,3015.57 v1@3337.37,3015.57
  Bottom Layer w10: v1@3251.37,1796.61 3251.37,1797.61 3444.37,1990.61 3444.37,2931.61 3359.37,3016.61 v1(3337.37,3016.61)
FSMC_A6: P1.18 U1.50 U2.23 | length 3265.2
  Top Layer w10: U2.23@2798.28,3551 2798.89,3551.61 3022.37,3551.61 v1(3080.87,3493.11) ; U1.50@3406.06,2256.4 4173.37,3023.7 v1(4173.37,3066.37) 4194,3087 ; 4183.69,3076.69 4199,3092 4406.98,3092 P1.18@4454.37,3044.61
  Bottom Layer w10: v1(3080.87,3493.11) 3172.37,3584.61 3385.37,3584.61 3483.37,3486.61 4025.37,3486.61 4172.37,3339.61 4172.37,3067.37 v1(4173.37,3066.37)
FSMC_A7: P1.15 U1.53 U2.22 | length 2581.5
  Top Layer w10: U2.22@3269.72,3551 v1(3373.37,3551) ; U1.53@3364.07,2298.42 3716.31,2650.66 3716.31,2797.31 4063.61,3144.61 P1.15@4354.37,3144.61
  Bottom Layer w10: v1(3373.37,3551) 3373.67,3551 3394.37,3530.3 3394.37,3530 3457.76,3466.61 4009.37,3466.61 4149.37,3326.61 v1(4149.37,3144.61)
FSMC_A8: P1.16 U1.54 U2.21 | length 2645.9
  Top Layer w10: U2.21@3270.72,3519.5 3371.27,3519.5 v1(3373.37,3521.61) ; U1.54@3350.15,2312.34 3698.31,2660.49 3698.31,2813.31 4074.61,3189.61 4409.37,3189.61 P1.16@4454.37,3144.61
  Bottom Layer w10: v1(3373.37,3521.61) 3448.37,3446.61 3998.83,3446.61 4128.37,3317.06 4128.37,3191.61 v1(4127.37,3190.61)
FSMC_A9: P1.13 U1.55 U2.20 | length 2471.5
  Top Layer w10: U2.20@3269.72,3488.01 U2.20@3270.72,3488.01 v1(3373.37,3488.01) ; U1.55@3336.23,2326.26 3680.31,2670.33 3680.31,2832.31 4092.61,3244.61 P1.13@4354.37,3244.61
  Bottom Layer w10: v1(3373.37,3488.01) 3433.77,3427.61 3990.37,3427.61 4107.37,3310.61 v1(4107.37,3243.61)
FSMC_A10: "2.4/2.8 LCD.2" P1.14 U1.56 U2.19 | length 4008
  Top Layer w10: 2317,3896 2369,3844 2369,3772.61 2409,3732.61 3107.83,3732.61 3241.83,3598.61 3394.37,3598.61 3459.37,3533.61 v1(3459.37,3406.61) ; U2.19@3270.72,3456.51 v1@3371.28,3456.51 ; U1.56@3322.31,2340.18 3661.37,2679.24 3661.37,2856.37 4094.61,3289.61 4409.37,3289.61 P1.14@4454.37,3244.61
  Bottom Layer w10: v1(3371.37,3456.61) 3421.37,3406.61 v1(3459.37,3406.61) 3977.39,3406.61 4079,3305 v1@4079,3277
  other v1: 4079,3274
FSMC_A11: P1.11 U1.57 U2.18 | length 2399.3
  Top Layer w10: U2.18@3270.72,3425.02 v1@3369.78,3425.02 ; U1.57@3308.39,2354.1 3643.37,2689.08 3643.37,2875.37 4112.61,3344.61 P1.11@4354.37,3344.61
  Bottom Layer w10: v1@3371.37,3427.61 3416.37,3382.61 3952.39,3382.61 v1@4048,3287
  other v1: 4053,3284 3371.37,3426.61
FSMC_A12: P2.13 U1.87 U2.28 | length 2423.5
  Top Layer w10: P2.13@1779.37,3229.61 1829.37,3279.61 1899.37,3279.61 ; 1900.37,3279.61 v1(2177.37,3002.61) ; v1@2176.87,3002.11 2422.37,2756.61 2422.37,2583.61 2532.37,2473.61 2659.92,2473.61 U1.87@2765.77,2367.75 ; v1(2674.37,3419.61) 2699.37,3419.61 2725.46,3393.52 U2.28@2798.28,3393.52
  Bottom Layer w10: v1(2177.37,3002.61) 2209.37,3034.61 2209.37,3262.61 2366.37,3419.61 v1(2674.37,3419.61)
FSMC_A13: P2.14 U1.88 U2.27 | length 2321.5
  Top Layer w10: P2.14@1888.37,3229.61 v1(2137.37,2980.61) ; v1@2137.87,2981.11 2401.37,2717.61 2401.37,2576.61 2522.37,2455.61 2650.08,2455.61 U1.88@2751.85,2353.83 ; v1(2681.37,3448.61) 2705.37,3448.61 2728.96,3425.02 U2.27@2798.28,3425.02
  Bottom Layer w10: v1(2137.37,2980.61) 2137.37,3011.61 2188.37,3062.61 2188.37,3282.61 2354.37,3448.61 v1(2681.37,3448.61) v1@2682.37,3449.61
FSMC_A14: P2.15 U1.89 U2.26 | length 2480.7
  Top Layer w10: P2.15@1779.37,3129.61 1821.9,3172.13 1896.99,3172.13 v1(2108.37,2960.75) 2379.37,2689.75 2379.37,2549.61 2491.37,2437.61 2637.86,2437.61 2660.86,2414.61 2663.24,2414.61 U1.89@2737.93,2339.91 ; v1(2677.37,3479.61) 2713.37,3479.61 2736.46,3456.51 U2.26@2798.28,3456.51
  Bottom Layer w10: v1(2108.37,2960.75) 2108.37,3021.61 2165.37,3078.61 2165.37,3296.61 2348.37,3479.61 v1(2677.37,3479.61)
FSMC_A15: P2.16 U1.90 U2.25 | length 2392.9
  Top Layer w10: P2.16@1879.37,3129.61 P2.16@1889.37,3129.61 ; P2.16@1890.37,3129.61 v1(2080.37,2939.61) ; v1@2079.87,2939.11 2356.37,2662.61 2356.37,2537.52 2474.28,2419.61 2630.4,2419.61 U1.90@2724.01,2325.99 ; v1(2674.37,3509.61) 2728.37,3509.61 2749.97,3488.01 U2.25@2798.28,3488.01
  Bottom Layer w10: v1(2080.37,2939.61) 2080.37,3032.61 2145.37,3097.61 2145.37,3311.61 2343.37,3509.61 v1(2674.37,3509.61)
FSMC_A16: P2.8 U1.80 U2.42 | length 1773.8
  Top Layer w10: P2.8@1879.37,3529.61 1887.37,3529.61 2565.37,2851.61 2565.37,2763.06 U1.80@2862.97,2465.46 ; v1(2746.4,2952.57) U2.42@2797.28,2952.57
  Bottom Layer w10: v1(2523.37,2895.61) 2580.34,2952.57 v1(2746.4,2952.57)
FSMC_A17: P2.9 U1.81 U2.43 | length 1858.8
  Top Layer w10: P2.9@1779.37,3429.61 1821.9,3472.13 1905.84,3472.13 2545.37,2832.61 2545.37,2755.19 U1.81@2849.29,2451.27 ; v1(2743.9,2921.08) U2.43@2797.28,2921.08
  Bottom Layer w10: v1(2521.37,2855.61) 2586.84,2921.08 v1(2743.9,2921.08)
FSMC_A18: P2.10 U1.82 U2.44 | length 1710.8
  Top Layer w10: P2.10@1879.37,3429.61 1915.37,3429.61 v1(2524.37,2820.61) ; v1(2524.37,2820.61) 2524.34,2801.93 2524.34,2764.64 2524.34,2748.37 U1.82@2835.37,2437.35 ; v1(2742.39,2889.58) U2.44@2797.28,2889.58
  Bottom Layer w10: v1(2524.37,2820.61) 2593.35,2889.58 v1(2742.39,2889.58)
FSMC_D0: "2.4/2.8 LCD.6" P2.11 U1.85 U2.7 | length 3741
  Top Layer w10: P2.11@1779.37,3329.61 1821.9,3372.13 1896.99,3372.13 2462.37,2806.75 2462.37,2602.61 2555.37,2509.61 2679.6,2509.61 U1.85@2793.61,2395.59 2833.37,2355.83 v1(2833.37,2261.61) ; v1(3100.37,3000.61) 3180.37,3080.61 U2.7@3268.68,3080.61
  Bottom Layer w10: v1(2031.37,3237.61) 2031.37,3445.61 2241.76,3656 2393,3656 2467,3730 2467,3846 2517,3896 ; v1(2833.37,2261.61) 2916.37,2344.61 2976.91,2344.61 3100.37,2468.06 v1(3100.37,3000.61)
FSMC_D1: "2.4/2.8 LCD.7" P2.12 U1.86 U2.8 | length 3601.5
  Top Layer w10: P2.12@1879.37,3329.61 1897.37,3329.61 v1(2086.37,3140.61) ; v1@2085.87,3140.11 2444.37,2781.61 2444.37,2590.61 2543.37,2491.61 2669.76,2491.61 U1.86@2779.69,2381.67 2807.36,2354 v1(2807.37,2294.61) ; v1(3079.37,3017.61) 3171.82,3110.06 U2.8@3269.72,3110.06
  Bottom Layer w10: v1(2086.37,3140.61) 2088.37,3142.61 2088.37,3378.15 2280.22,3570 2458,3570 2617,3729 2617,3796 ; v1@2807.37,2296.61 2876.37,2365.61 2972.37,2365.61 3079.37,2472.61 v1(3079.37,3017.61)
FSMC_D2: "2.4/2.8 LCD.8" P2.33 U1.114 U2.9 | length 4240
  Top Layer w10: P2.33@1779.37,2229.61 1829.37,2279.61 1899.37,2279.61 2359.37,1819.61 2495.51,1819.61 U1.114@2542.83,1866.92 ; v1(2457,3636) 2505.39,3587.61 3021.37,3587.61 3112.37,3496.61 3112.37,3242.61 3213.42,3141.55 U2.9@3270.72,3141.55
  Bottom Layer w10: v1(2029.37,2153.61) 2029.37,3182.61 2070.37,3223.61 2070.37,3408.37 2267,3605 2425,3605 2569,3749 2569,3848 2617,3896
FSMC_D3: "2.4/2.8 LCD.9" P2.34 U1.115 U2.10 | length 4003.8
  Top Layer w10: P2.34@1879.37,2229.61 1894.37,2229.61 v1(2051.37,2072.61) ; v1@2050.87,2072.11 2321.37,1801.61 2505.35,1801.61 U1.115@2556.75,1853 ; v1(2593.37,3626.61) 2613.37,3606.61 3039.37,3606.61 3130.37,3515.61 3130.37,3283.21 3240.53,3173.05 U2.10@3270.72,3173.05
  Bottom Layer w10: v1(2051.37,2072.61) 2051.37,3051.61 2121.37,3121.61 2121.37,3371.61 2292.37,3542.61 2509.37,3542.61 v1(2593.37,3626.61) 2717,3750.24 2717,3796
FSMC_D4: "2.4/2.8 LCD.10" P1.12 U1.58 U2.13 | length 3511.5
  Top Layer w10: v1@2773,3628.61 3052.37,3628.61 3148.37,3532.61 3148.37,3334.61 3215.44,3267.54 U2.13@3270.72,3267.54 ; U2.13@3273.65,3265.61 v1(3353.37,3265.61) ; U1.58@3294.48,2368.02 3625.37,2698.91 3625.37,2889.37 4130.61,3394.61 4404.37,3394.61 ; 4404.83,3394.61 4404.37,3394.61 ; P1.12@4454.37,3344.61 4404.37,3394.61
  Bottom Layer w10: 2717,3896 2773,3840 v1(2773,3629) ; v1(3353.37,3265.61) 3373.37,3265.61 3414.37,3306.61 3886.39,3306.61 v1@3964.5,3228.5
  other v1: 3964,3228
FSMC_D5: "2.4/2.8 LCD.11" P1.9 U1.59 U2.14 | length 3218.6
  Top Layer w10: v1@2813,3649.61 3065.37,3649.61 3166.37,3548.61 3166.37,3348.61 3215.94,3299.03 U2.14@3270.72,3299.03 ; U2.14@3273.3,3298.61 v1(3370.37,3298.61) ; U1.59@3280.56,2381.94 3607.37,2708.75 3607.37,2903.37 4148.61,3444.61 P1.9@4354.37,3444.61
  Bottom Layer w10: v1(2813,3650) 2813,3792 ; v1(3370.37,3298.61) 3396.37,3324.61 3900.39,3324.61 v1@3964.5,3260.5
  other v1: 3965,3260
FSMC_D6: "2.4/2.8 LCD.12" P1.10 U1.60 U2.15 | length 3415.2
  Top Layer w10: v1@2861,3671.61 3081.37,3671.61 3184.37,3568.61 3184.37,3366.61 3220.45,3330.53 U2.15@3269.72,3330.53 ; U1.60@3266.64,2395.86 3587.37,2716.59 3587.37,2915.37 v1(3964,3292) 4171.61,3499.61 4399.37,3499.61 P1.10@4454.37,3444.61 ; U2.15@3270.72,3330.53 3270.8,3330.61 v1(3370.37,3330.61)
  Bottom Layer w10: 2817,3896 2861,3852 v1(2861,3671) ; v1@3370.37,3331.61 3382.14,3343.37 3912.63,3343.37 v1(3964,3292)
FSMC_D7: "2.4/2.8 LCD.13" P1.7 U1.63 U2.16 | length 3120.4
  Top Layer w10: v1@2887,3692.61 3091.37,3692.61 3202.37,3581.61 3202.37,3390.44 3230.79,3362.02 U2.16@3270.72,3362.02 v1(3340.37,3362.02) ; U1.63@3224.88,2437.62 3490.37,2703.11 3490.37,2910.61 v1@3936.37,3356.61 ; v1@3942.44,3361.37 4125.67,3544.61 P1.7@4354.37,3544.61
  Bottom Layer w10: v1(2887,3693) 2887,3766 2917,3796 ; v1@3341.02,3361.37 v1(3942.14,3361.37)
